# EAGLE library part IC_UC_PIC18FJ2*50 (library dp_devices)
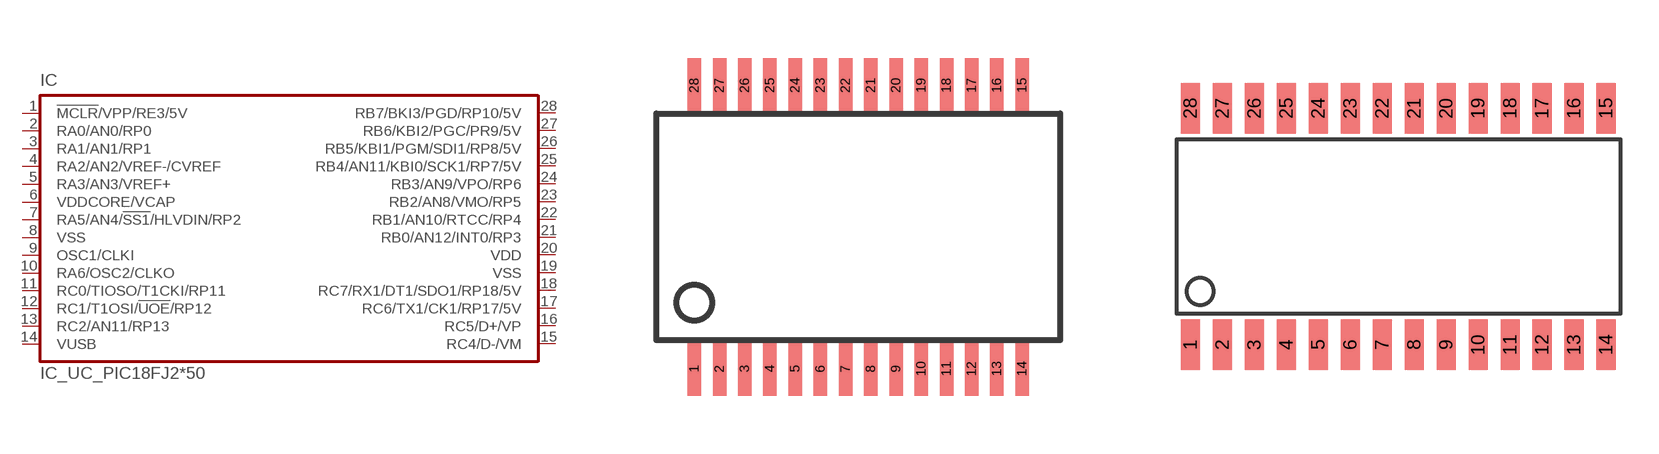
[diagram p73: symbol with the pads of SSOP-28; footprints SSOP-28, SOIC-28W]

Designator prefix IC

## IC_UC_PIC18FJ250-SSOP-28 (PIC18FJ2X50: PIC18FJ2X50)  [SSOP-28]
1  !MCLR!/VPP/RE3/5V  in
2  RA0/AN0/RP0
3  RA1/AN1/RP1
4  RA2/AN2/VREF-/CVREF
5  RA3/AN3/VREF+
6  VDDCORE/VCAP
7  RA5/AN4/!SS1!/HLVDIN/RP2
8  VSS  pwr
9  OSC1/CLKI  in
10  RA6/OSC2/CLKO  out
11  RC0/TIOSO/T1CKI/RP11
12  RC1/T1OSI/!UOE!/RP12
13  RC2/AN11/RP13
14  VUSB
15  RC4/D-/VM
16  RC5/D+/VP
17  RC6/TX1/CK1/RP17/5V
18  RC7/RX1/DT1/SDO1/RP18/5V
19  VSS  pwr
20  VDD  pwr
21  RB0/AN12/INT0/RP3
22  RB1/AN10/RTCC/RP4
23  RB2/AN8/VMO/RP5
24  RB3/AN9/VPO/RP6
25  RB4/AN11/KBI0/SCK1/RP7/5V
26  RB5/KBI1/PGM/SDI1/RP8/5V
27  RB6/KBI2/PGC/PR9/5V
28  RB7/BKI3/PGD/RP10/5V

## IC_UC_PIC18FJ250-SOIC-28-W  [SOIC-28W]
Pads as for SSOP-28

## Footprint SSOP-28 (pad centres in mm)
SSOP28
smd 0.348 x 1.397: 1 -4.225,-3.656; 2 -3.575,-3.656; 3 -2.925,-3.656; 4 -2.275,-3.656; 5 -1.625,-3.656; 6 -0.975,-3.656; 7 -0.325,-3.656; 8 0.325,-3.656; 9 0.975,-3.656; 10 1.625,-3.656; 11 2.275,-3.656; 12 2.925,-3.656; 13 3.575,-3.656; 14 4.225,-3.656; 15 4.225,3.656; 16 3.575,3.656; 17 2.925,3.656; 18 2.275,3.656; 19 1.625,3.656; 20 0.975,3.656; 21 0.325,3.656; 22 -0.325,3.656; 23 -0.975,3.656; 24 -1.625,3.656; 25 -2.275,3.656; 26 -2.925,3.656; 27 -3.575,3.656; 28 -4.225,3.656

## Footprint SOIC-28W (pad centres in mm)
smd 0.762 x 2: 1 -8.89,-4.7; 2 -7.62,-4.7; 3 -6.35,-4.7; 4 -5.08,-4.7; 5 -3.81,-4.7; 6 -2.54,-4.7; 7 -1.27,-4.7; 8 0,-4.7; 9 1.27,-4.7; 10 2.54,-4.7; 11 3.81,-4.7; 12 5.08,-4.7; 13 6.35,-4.7; 14 7.62,-4.7; 15 7.62,4.7; 16 6.35,4.7; 17 5.08,4.7; 18 3.81,4.7; 19 2.54,4.7; 20 1.27,4.7; 21 0,4.7; 22 -1.27,4.7; 23 -2.54,4.7; 24 -3.81,4.7; 25 -5.08,4.7; 26 -6.35,4.7; 27 -7.62,4.7; 28 -8.89,4.7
